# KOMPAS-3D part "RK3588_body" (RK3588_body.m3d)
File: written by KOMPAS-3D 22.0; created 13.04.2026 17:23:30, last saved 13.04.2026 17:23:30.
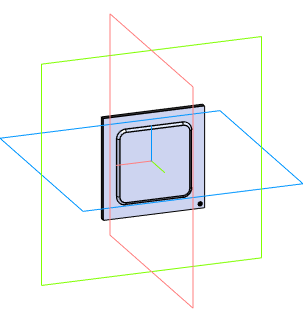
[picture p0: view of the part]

Document properties: Автор: Andrey; Полное имя файла: C:\Users\User1\Documents\RK3588_body.m3d

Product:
- Part/product: RK3588_body

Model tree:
1. Операция без истории:1
2. Операция без истории:2
3. Операция без истории:3
4. Операция без истории:4
5. Операция без истории:5
6. Операция без истории:6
